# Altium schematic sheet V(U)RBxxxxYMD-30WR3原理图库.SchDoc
size 127 x 99 mm
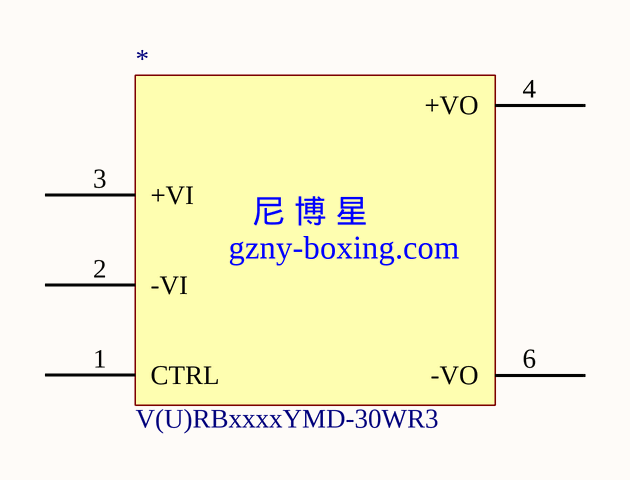
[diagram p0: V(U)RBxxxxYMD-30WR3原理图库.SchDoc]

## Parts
*  V(U)RBxxxxYMD-30WR3

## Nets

Not connected (* = marked no-connect by the designer): * 1(CTRL) 2(-VI) 3(+VI) 4(+VO) 6(-VO)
